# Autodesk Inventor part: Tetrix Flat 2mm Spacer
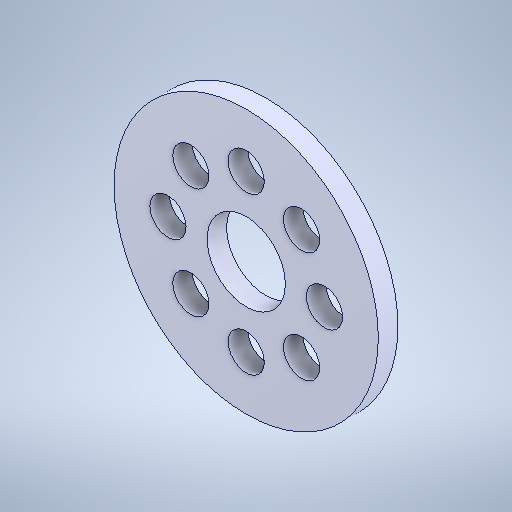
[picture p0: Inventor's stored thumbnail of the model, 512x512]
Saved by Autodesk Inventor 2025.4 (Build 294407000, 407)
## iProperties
Created: 2021-10
Part Number: Tetrix Flat 2mm Spacer
Material: Genérico
Document SubType Name: Modeling
Designer: usuario
Density: 1 g/cm^3
Appearance: Valor por defecto
Author: usuario
Sending System: SolidWorks 2016
Last Author: LENOVO
Last Saved: 2021-10-23
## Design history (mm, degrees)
feature "Boss-Extrude1"
node "Plane1"
node "Sólido1"
